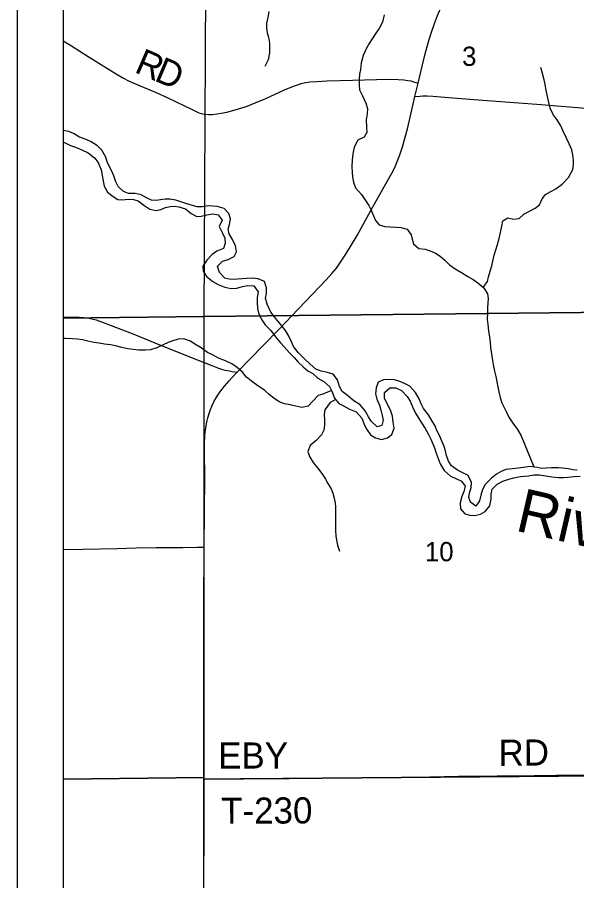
# Model space of a CAD drawing. Extents: x 0 to 34, y 0 to 22.
# Drawn here: x 2 to 3.216, y 16.037 to 17.915 of the extents above; entities that cross this region are included whole.
import ezdxf

# ---------------------------------------------------------------- set-up
doc = ezdxf.new("R2010")
doc.units = 0
for name, color, linetype in [('Default', 7, 'Continuous'), ('GM_X_Major_River', 7, 'Continuous'), ('GM_X_Major_River_Text', 7, 'Continuous'), ('GM_X_Minor_River', 7, 'Continuous'), ('GM_X_Section', 7, 'Continuous'), ('GM_X_Section_Text', 7, 'Continuous'), ('GM_X_State_Route', 7, 'Continuous'), ('GM_X_Township_Road', 7, 'Continuous'), ('GM_X_Township_Road_Text', 7, 'Continuous'), ('SH_Cut_Line', 7, 'Continuous'), ('SH_Data', 7, 'Continuous')]:
    doc.layers.add(name, color=color, linetype=linetype)

msp = doc.modelspace()

# ---------------------------------------------------------------- linework, layer by layer
at = {"layer": 'Default'}
for points in [[(2.1, 18.2545), (2.1, 17.2601), (2.406, 17.2639), (2.4116, 18.261)], [(2.1, 17.2601), (2.1, 16.2572), (2.4062, 16.2613), (2.406, 17.2639)], [(2.1, 16.2572), (2.1, 15.2441), (2.4044, 15.2506), (2.4062, 16.2575), (2.4062, 16.2613)]]:
    msp.add_lwpolyline(points, close=True, dxfattribs=at)
msp.add_lwpolyline([(2.1, 18.2607), (2.1, 14.1)], dxfattribs=at)
at = {"layer": 'GM_X_Major_River'}
for points in [[(2.4586, 17.4538), (2.461, 17.464), (2.4634, 17.4765), (2.4601, 17.4876), (2.4496, 17.4991), (2.4348, 17.5035), (2.4253, 17.5039), (2.4151, 17.5044), (2.4029, 17.5027), (2.3908, 17.5024), (2.3779, 17.506), (2.3662, 17.5096), (2.3556, 17.5131), (2.3443, 17.5166), (2.3314, 17.5194), (2.3215, 17.5188), (2.3116, 17.5174), (2.3021, 17.5164), (2.2919, 17.5169), (2.282, 17.5215), (2.2692, 17.5285), (2.256, 17.5317), (2.2415, 17.5315), (2.231, 17.5358), (2.2193, 17.5466), (2.2141, 17.5565), (2.2097, 17.5698), (2.2034, 17.5843), (2.196, 17.5985), (2.1923, 17.6107), (2.1841, 17.6256), (2.1747, 17.6352), (2.1608, 17.6437), (2.1495, 17.6491), (2.1351, 17.6542), (2.1219, 17.662), (2.1117, 17.6666), (2.1, 17.6684)], [(2.1, 17.6433), (2.1027, 17.6421), (2.1155, 17.6362), (2.1269, 17.6319), (2.1401, 17.6261), (2.1544, 17.6198), (2.168, 17.609), (2.1758, 17.5991), (2.1825, 17.5827), (2.1846, 17.5705), (2.1864, 17.5591), (2.1889, 17.5477), (2.1964, 17.5343), (2.2081, 17.5247), (2.2186, 17.5185), (2.2281, 17.518), (2.241, 17.5193), (2.2528, 17.5185), (2.263, 17.5153), (2.2754, 17.5064), (2.2878, 17.4972), (2.3022, 17.4943), (2.3121, 17.4969), (2.3221, 17.5009), (2.332, 17.5035), (2.3414, 17.5038), (2.3513, 17.5021), (2.3653, 17.4978), (2.3777, 17.4882), (2.3902, 17.4816), (2.3997, 17.4818), (2.4118, 17.4847), (2.4248, 17.4872), (2.4369, 17.4848), (2.4455, 17.4737), (2.4389, 17.4594), (2.4463, 17.4452), (2.4508, 17.4345), (2.4522, 17.4235), (2.4486, 17.4118), (2.4341, 17.4059), (2.4238, 17.3988), (2.4119, 17.3868), (2.4034, 17.3732)], [(3.1152, 16.9379), (3.0993, 16.9353), (3.0898, 16.9339), (3.0765, 16.9326), (3.0621, 16.9308), (3.0518, 16.9268), (3.0415, 16.9208), (3.0307, 16.9122), (3.0169, 16.8983), (3.0115, 16.8874), (3.0076, 16.8756), (3.0044, 16.8631), (2.997, 16.8511), (2.985, 16.8603), (2.9813, 16.8699), (2.9829, 16.8797), (2.9869, 16.8918), (2.9877, 16.9028), (2.9799, 16.9177), (2.9667, 16.9247), (2.9569, 16.9298), (2.9441, 16.939), (2.937, 16.949), (2.933, 16.9616), (2.9308, 16.9715), (2.9279, 16.9814), (2.9234, 16.9913), (2.9175, 17.0054), (2.9119, 17.0161), (2.9082, 17.026), (2.9019, 17.0363), (2.8937, 17.0497), (2.8832, 17.0639), (2.878, 17.0738), (2.8736, 17.0849), (2.8654, 17.0983), (2.8534, 17.1121), (2.8417, 17.1183), (2.8319, 17.1222), (2.8198, 17.1258), (2.8072, 17.127), (2.7962, 17.1264), (2.7844, 17.1208), (2.7801, 17.1091), (2.7784, 17.0959), (2.7817, 17.084), (2.7873, 17.0711), (2.7902, 17.0604), (2.7931, 17.0486), (2.7953, 17.0387), (2.7921, 17.0266), (2.7826, 17.024), (2.769, 17.036), (2.7638, 17.0459), (2.7564, 17.0585), (2.7451, 17.0719), (2.7316, 17.0808), (2.718, 17.0924), (2.706, 17.1009), (2.7004, 17.1116), (2.696, 17.1264), (2.6863, 17.1383), (2.6742, 17.1419), (2.6609, 17.1451), (2.6492, 17.1494), (2.6364, 17.1605), (2.6233, 17.1728), (2.6105, 17.1859), (2.6004, 17.1989), (2.5959, 17.2085), (2.5893, 17.2226), (2.5829, 17.2333), (2.5724, 17.2471), (2.5616, 17.2601), (2.5515, 17.2735), (2.5433, 17.2907), (2.5393, 17.304), (2.5417, 17.3139), (2.5418, 17.326), (2.5374, 17.3398), (2.5238, 17.346), (2.5109, 17.3473), (2.498, 17.3467), (2.4885, 17.346), (2.479, 17.345), (2.4642, 17.3444), (2.4513, 17.3476), (2.4397, 17.3599), (2.4349, 17.3736), (2.4464, 17.3845), (2.4586, 17.3877), (2.4712, 17.3944), (2.4766, 17.4046), (2.4741, 17.4176), (2.4678, 17.4317), (2.4607, 17.4439), (2.4586, 17.4538)], [(2.4034, 17.3732), (2.4037, 17.3626), (2.4111, 17.3507), (2.4254, 17.3399), (2.4364, 17.3337), (2.4511, 17.3275), (2.4651, 17.3246), (2.4773, 17.3256), (2.4895, 17.3289), (2.5013, 17.3314), (2.5142, 17.3305), (2.5235, 17.3175), (2.5218, 17.305), (2.5217, 17.2951), (2.5223, 17.2814), (2.5245, 17.2719), (2.5301, 17.2586), (2.5386, 17.2459), (2.551, 17.2333), (2.5615, 17.2195), (2.5724, 17.2068), (2.581, 17.1969), (2.5915, 17.1846), (2.602, 17.1746), (2.6106, 17.1646), (2.6211, 17.1542), (2.6313, 17.1454), (2.6422, 17.1396), (2.6535, 17.1296), (2.6663, 17.1222), (2.6784, 17.1118), (2.6836, 17.1015), (2.6899, 17.0866), (2.6988, 17.0747), (2.709, 17.0693), (2.7219, 17.0623), (2.7366, 17.0565), (2.7486, 17.0427), (2.7545, 17.0274), (2.7597, 17.0178), (2.7676, 17.0067), (2.7789, 16.9998), (2.7917, 16.9962), (2.8047, 16.9999), (2.8143, 17.0073), (2.819, 17.0213), (2.8172, 17.0343), (2.8155, 17.0468), (2.8111, 17.0598), (2.8051, 17.0724), (2.7984, 17.0861), (2.7982, 17.0987), (2.8101, 17.1084), (2.8226, 17.109), (2.8351, 17.1032), (2.8478, 17.0901), (2.8542, 17.0794), (2.859, 17.0676), (2.8653, 17.0538), (2.8712, 17.0443), (2.8787, 17.0324), (2.8865, 17.0202), (2.894, 17.0072), (2.8988, 16.9973), (2.907, 16.9782), (2.9106, 16.9664), (2.9147, 16.9549), (2.9191, 16.9431), (2.928, 16.929), (2.942, 16.9163), (2.9518, 16.912), (2.9654, 16.9057), (2.9736, 16.895), (2.9704, 16.8833), (2.9665, 16.8727), (2.9629, 16.8587), (2.9632, 16.8458), (2.9726, 16.8347), (2.9839, 16.8319), (2.9942, 16.8314), (3.0071, 16.8339), (3.017, 16.8395), (3.0274, 16.8523), (3.0302, 16.867), (3.03, 16.8777), (3.032, 16.8883), (3.0431, 16.8995), (3.0557, 16.9058), (3.0683, 16.9103), (3.0793, 16.9128), (3.0938, 16.9157), (3.1109, 16.9174)], [(3.2172, 16.9295), (3.2077, 16.9303), (3.1983, 16.9322), (3.1854, 16.9338), (3.1759, 16.9346), (3.1615, 16.935), (3.1497, 16.934), (3.1398, 16.9336), (3.1304, 16.9352), (3.1152, 16.9379)], [(3.1109, 16.9174), (3.1231, 16.9193), (3.1352, 16.9192), (3.1492, 16.9176), (3.1618, 16.9153), (3.1762, 16.9137), (3.1875, 16.914), (3.197, 16.9147), (3.2107, 16.9158), (3.2236, 16.9165)]]:
    msp.add_lwpolyline(points, dxfattribs=at)
at = {"layer": 'GM_X_Minor_River'}
for points in [[(2.5466, 17.9271), (2.5446, 17.9142), (2.5414, 17.9021), (2.5416, 17.8911), (2.5434, 17.8812), (2.5464, 17.8716), (2.5481, 17.8587), (2.5484, 17.8481), (2.5479, 17.8371), (2.5454, 17.8219), (2.5381, 17.8079)], [(2.7978, 17.92), (2.7939, 17.9045), (2.7865, 17.8905), (2.7796, 17.88), (2.7711, 17.8679), (2.7649, 17.8574), (2.7591, 17.8476), (2.7521, 17.8313), (2.7477, 17.8158), (2.7457, 17.8014), (2.744, 17.7908), (2.7431, 17.7801), (2.743, 17.7669), (2.744, 17.757), (2.7503, 17.744), (2.7574, 17.728), (2.761, 17.7161), (2.7609, 17.7044), (2.7585, 17.6919), (2.7594, 17.6755), (2.7601, 17.6641), (2.7539, 17.6543), (2.7405, 17.6477), (2.7324, 17.6322), (2.7292, 17.6174), (2.7279, 17.6045), (2.7274, 17.5897), (2.728, 17.5779), (2.729, 17.5669), (2.7308, 17.5559), (2.7352, 17.5441), (2.7483, 17.5291), (2.7569, 17.5165), (2.764, 17.505), (2.7696, 17.4951), (2.7744, 17.4832), (2.7788, 17.4729), (2.7863, 17.463)], [(3.1009, 17.4863), (3.1255, 17.4993), (3.1354, 17.5068), (3.1411, 17.5197), (3.1484, 17.5295), (3.1598, 17.5359), (3.1704, 17.5416), (3.1845, 17.5521), (3.1982, 17.5665), (3.2074, 17.5839), (3.209, 17.5942), (3.209, 17.6037), (3.2076, 17.6158), (3.2054, 17.6268), (3.1994, 17.6398), (3.1941, 17.6519), (3.1862, 17.6687), (3.1813, 17.679), (3.1734, 17.6915), (3.1655, 17.7022), (3.1584, 17.717), (3.1554, 17.7292), (3.1528, 17.7425), (3.1498, 17.7554), (3.1476, 17.7695), (3.145, 17.779), (3.142, 17.7923), (3.1379, 17.8056)], [(3.013, 17.3269), (3.0218, 17.3403), (3.0246, 17.3505), (3.0282, 17.3622), (3.0313, 17.3743), (3.0337, 17.3842), (3.0365, 17.3974), (3.0401, 17.4092), (3.044, 17.4205), (3.0475, 17.4334), (3.0507, 17.4466), (3.0532, 17.4603), (3.0552, 17.472), (3.0663, 17.4787), (3.0788, 17.4755), (3.0913, 17.4773), (3.1009, 17.4863)], [(2.7863, 17.463), (2.7992, 17.4598), (2.8109, 17.4593), (2.8235, 17.4584), (2.8337, 17.4575), (2.8477, 17.4539), (2.8563, 17.4413), (2.8585, 17.4318), (2.861, 17.4222), (2.8731, 17.4118), (2.8867, 17.4102), (2.8977, 17.407), (2.909, 17.4016), (2.9192, 17.395), (2.9293, 17.3861), (2.9395, 17.3765), (2.9519, 17.3673), (2.9659, 17.3595), (2.9791, 17.351), (2.9907, 17.3444), (3.0013, 17.3375), (3.0141, 17.3259), (3.0219, 17.3129), (3.0233, 17.303), (3.0232, 17.2932), (3.0223, 17.2837), (3.0218, 17.2708), (3.0217, 17.2579), (3.0227, 17.2468), (3.0241, 17.2324), (3.0266, 17.2191), (3.0276, 17.2081), (3.029, 17.1966), (3.0307, 17.1826), (3.0321, 17.1727), (3.0343, 17.1597), (3.0375, 17.1449), (3.0404, 17.1331), (3.0447, 17.111), (3.0465, 17.1), (3.0494, 17.0874), (3.0534, 17.076), (3.0631, 17.0558), (3.0683, 17.0451), (3.0772, 17.0317), (3.087, 17.0179), (3.0952, 17.0045), (3.1226, 16.9366)], [(2.6827, 17.1032), (2.6641, 17.0949), (2.6542, 17.092), (2.6423, 17.08), (2.6323, 17.0691), (2.6183, 17.0662), (2.6054, 17.0686), (2.5933, 17.0714), (2.5812, 17.0738), (2.5691, 17.0785), (2.5578, 17.0866), (2.548, 17.0936), (2.5371, 17.1039), (2.5231, 17.1132), (2.5118, 17.1209), (2.4983, 17.1317), (2.4897, 17.1425), (2.478, 17.1528), (2.4663, 17.1613), (2.4527, 17.1676), (2.4376, 17.1734), (2.424, 17.1804), (2.4135, 17.1855), (2.3995, 17.1955), (2.3863, 17.204), (2.3765, 17.2102), (2.3622, 17.2153), (2.35, 17.2143), (2.3378, 17.211), (2.3279, 17.207), (2.3168, 17.2025), (2.3031, 17.1955), (2.2898, 17.1915), (2.2787, 17.1904), (2.2636, 17.1906), (2.2526, 17.1919), (2.2404, 17.1939), (2.2276, 17.1967), (2.2136, 17.1999), (2.2026, 17.202), (2.1897, 17.204), (2.1783, 17.2057), (2.1662, 17.2077), (2.1533, 17.2101), (2.1416, 17.2129), (2.131, 17.2146), (2.12, 17.2154), (2.1048, 17.216), (2.1, 17.2163)], [(2.6922, 17.0835), (2.6799, 17.0765), (2.6683, 17.061), (2.6674, 17.0504), (2.6677, 17.0394), (2.668, 17.0276), (2.6663, 17.0163), (2.6613, 17.0064), (2.6494, 16.9944), (2.6363, 16.9832), (2.6313, 16.9703), (2.6349, 16.9593), (2.6431, 16.9463), (2.6525, 16.9344), (2.6641, 16.9198), (2.6701, 16.9103), (2.6753, 16.9007), (2.682, 16.8893), (2.6861, 16.8797), (2.689, 16.8687), (2.6911, 16.8588), (2.6914, 16.8489), (2.6916, 16.8341), (2.6914, 16.8109), (2.6916, 16.7984), (2.6926, 16.787), (2.6936, 16.7771), (2.6958, 16.7668), (2.7002, 16.7531)]]:
    msp.add_lwpolyline(points, dxfattribs=at)
at = {"layer": 'GM_X_Section'}
for points in [[(2.4116, 18.261), (2.4434, 18.2628), (3.4263, 18.2757), (3.4308, 17.2748), (2.406, 17.2639)], [(3.4308, 17.2748), (3.434, 16.2663), (2.4062, 16.2575), (2.4062, 16.2613), (2.406, 17.2639)], [(2.4062, 16.2575), (3.434, 16.2663), (3.4363, 15.7808), (3.4219, 15.2567), (2.4044, 15.2506)]]:
    msp.add_lwpolyline(points, close=True, dxfattribs=at)
at = {"layer": 'GM_X_State_Route'}
for points in [[(2.8645, 17.7422), (2.8715, 17.7718), (2.8744, 17.7841), (2.8809, 17.8113), (2.8866, 17.8355), (2.8933, 17.8595), (2.8997, 17.8803), (2.9068, 17.9009), (2.9134, 17.9184), (2.9205, 17.9356), (2.9338, 17.9637), (2.9628, 18.0222), (2.976, 18.0503), (2.9938, 18.09), (3.0325, 18.1783), (3.0513, 18.2209), (3.0583, 18.2381), (3.0624, 18.2498), (3.0668, 18.2647), (3.0684, 18.2709)], [(2.4781, 17.143), (2.5078, 17.1733), (2.5336, 17.2003), (2.5684, 17.2358), (2.6115, 17.2806), (2.6717, 17.3434), (2.6841, 17.3572), (2.6936, 17.3694), (2.7026, 17.382), (2.713, 17.3974), (2.7245, 17.4159), (2.7386, 17.4402), (2.7729, 17.5028), (2.8141, 17.5759), (2.8211, 17.5897), (2.8259, 17.6011), (2.8314, 17.6156), (2.8374, 17.6332), (2.8427, 17.6511), (2.8488, 17.6752), (2.8616, 17.7297), (2.8645, 17.7422)], [(2.8645, 17.7422), (2.8754, 17.7432), (2.8817, 17.7439), (2.891, 17.744), (2.9035, 17.7435), (2.9468, 17.7398), (3.0118, 17.7344), (3.1388, 17.7251), (3.2441, 17.7166), (3.2627, 17.7156), (3.2751, 17.7154), (3.2875, 17.7158), (3.2967, 17.7166), (3.312, 17.7187), (3.3672, 17.7277), (3.401, 17.7333), (3.4299, 17.7377), (3.4308, 17.7378)], [(2.1, 17.2627), (2.1221, 17.2628), (2.1345, 17.2625), (2.1439, 17.2619), (2.1532, 17.2607), (2.1624, 17.2589), (2.1714, 17.2565), (2.1832, 17.2525), (2.2499, 17.2267), (2.2987, 17.2067), (2.3766, 17.1757), (2.4227, 17.157), (2.4372, 17.1515), (2.446, 17.1487), (2.452, 17.1471), (2.4611, 17.1454), (2.4672, 17.1445), (2.4781, 17.143)], [(2.4056, 15.9968), (2.4055, 16.0932), (2.4057, 16.1708), (2.4057, 16.1829), (2.4057, 16.2577), (2.4056, 16.3635), (2.4053, 16.6332), (2.4065, 16.7625), (2.4068, 16.839), (2.4077, 16.9136), (2.4071, 16.9695), (2.4072, 16.9881), (2.4078, 17.0037), (2.4086, 17.013), (2.4103, 17.0254), (2.412, 17.0346), (2.4141, 17.0437), (2.4168, 17.0527), (2.4199, 17.0615), (2.4235, 17.0702), (2.4276, 17.0786), (2.4322, 17.0868), (2.4372, 17.0947), (2.4425, 17.1024), (2.4501, 17.1123), (2.4603, 17.1241), (2.473, 17.1378), (2.4781, 17.143)]]:
    msp.add_lwpolyline(points, dxfattribs=at)
at = {"layer": 'GM_X_Township_Road'}
for points in [[(2.1, 17.8639), (2.1175, 17.8529), (2.1544, 17.8298), (2.2174, 17.79), (2.2308, 17.7821), (2.2418, 17.7764), (2.2531, 17.7711), (2.276, 17.7617), (2.3019, 17.751), (2.3273, 17.7393), (2.3636, 17.7219), (2.3804, 17.714), (2.3943, 17.7072), (2.4002, 17.7054), (2.4063, 17.7041), (2.4155, 17.7031), (2.4186, 17.703), (2.4247, 17.7033), (2.434, 17.7044), (2.4432, 17.7059), (2.4553, 17.7085), (2.4734, 17.7132), (2.4883, 17.7176), (2.5, 17.7216), (2.5173, 17.7285), (2.5401, 17.7384), (2.5826, 17.7574), (2.6027, 17.7657), (2.6115, 17.7689), (2.6174, 17.7707), (2.6265, 17.7727), (2.6357, 17.774), (2.6512, 17.7752), (2.6729, 17.7762), (2.7288, 17.7779), (2.7812, 17.7796), (2.8121, 17.7799), (2.8276, 17.7796), (2.84, 17.7788), (2.8492, 17.7775), (2.8553, 17.7763), (2.8613, 17.7746), (2.8715, 17.7718)], [(2.1, 16.7573), (2.1433, 16.7578), (2.2179, 16.7594), (2.2583, 16.7606), (2.3017, 16.7612), (2.36, 16.7614), (2.3911, 16.7621), (2.4065, 16.7625)], [(2.4057, 16.2577), (2.4147, 16.2579), (2.454, 16.2585), (2.4851, 16.2588), (2.5224, 16.2589), (2.5317, 16.259), (2.5472, 16.2589), (2.5876, 16.2589), (2.5907, 16.2592), (2.6559, 16.2599), (2.7053, 16.2602), (2.7891, 16.2612), (2.8294, 16.2613), (2.8658, 16.262), (2.9593, 16.2638), (2.9997, 16.2643), (3.0432, 16.2646), (3.1239, 16.2652), (3.1705, 16.2659), (3.1985, 16.2662), (3.3072, 16.2671), (3.332, 16.2672), (3.3824, 16.2678)]]:
    msp.add_lwpolyline(points, dxfattribs=at)
at = {"layer": 'SH_Cut_Line'}
msp.add_lwpolyline([(2.1, 20.9), (2.1, 14.1), (7.4893, 14.1)], dxfattribs=at)
at = {"layer": 'SH_Data'}
for p, q in [((2, 21), (2, 14)), ((2.1, 20.9), (2.1, 14.1))]:
    msp.add_line(p, q, dxfattribs=at)

# ---------------------------------------------------------------- texts
at = {"layer": 'GM_X_Major_River_Text'}
msp.add_text('River', height=0.09473, rotation=347.0559, dxfattribs=at).set_placement((3.08, 16.7987))
at = {"layer": 'GM_X_Section_Text'}
for s, height, p in [('3', 0.0419, (2.9669, 17.809)), ('10', 0.04186, (2.8861, 16.7315))]:
    msp.add_text(s, height=height, rotation=0, dxfattribs=at).set_placement(p)
at = {"layer": 'GM_X_Township_Road_Text'}
for s, height, rotation, p in [('R', 0.0568, 336.7409, (2.2525, 17.7962)), ('D', 0.0568, 337.0711, (2.2957, 17.7777)), ('RD', 0.05682, 0.4936, (3.0463, 16.2864)), ('EBY', 0.05682, 0, (2.4365, 16.2806)), ('T-230', 0.05682, 0.2901, (2.4432, 16.1603))]:
    msp.add_text(s, height=height, rotation=rotation, dxfattribs=at).set_placement(p)

doc.saveas('drawing.dxf')
